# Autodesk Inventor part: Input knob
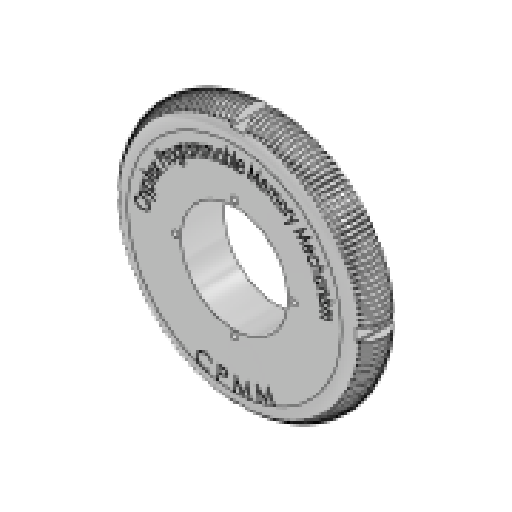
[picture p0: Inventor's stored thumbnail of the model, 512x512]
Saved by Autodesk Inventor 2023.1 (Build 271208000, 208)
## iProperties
Created: 2020-01
Part Number: Input knob
Material: Aluminum 6061
Document SubType Name: Modeling
Designer: ftrauzettel
Density: 2.7 g/cm^3
Appearance: Aluminum - Polished
Sending System: SolidWorks 2016
Last Author: Pam
Last Saved: 2020-02-24
Author: ftrauzettel
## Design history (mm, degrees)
feature "CirPattern3"
body "Solid1"
